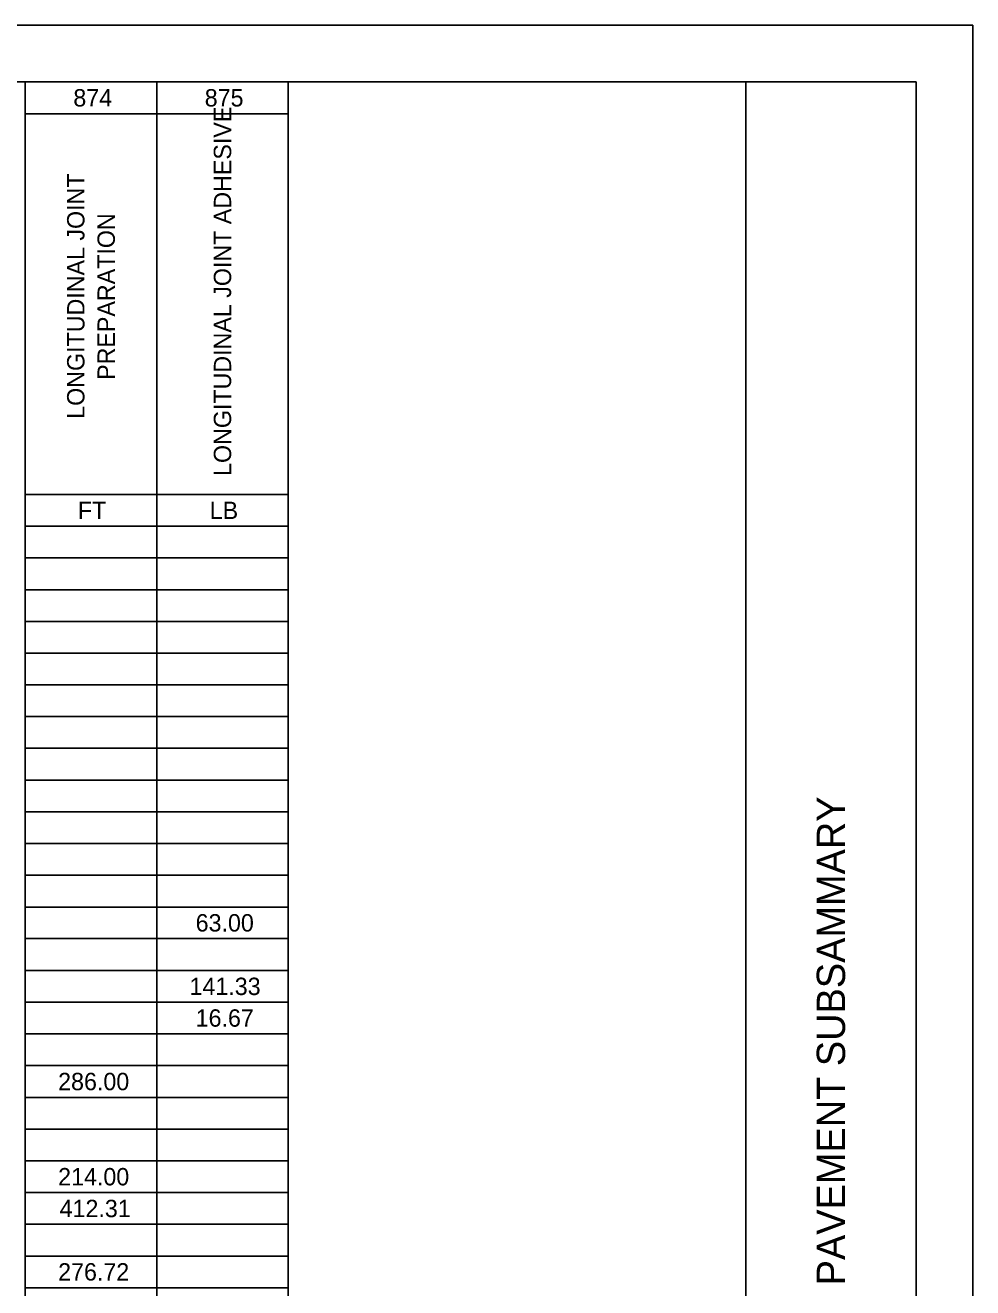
# Model space of a CAD drawing. Extents: x 0 to 34, y 0 to 22.
# Drawn here: x 25.65 to 34, y 10.87 to 22 of the extents above; entities that cross this region are included whole.
import ezdxf

# ---------------------------------------------------------------- set-up
doc = ezdxf.new("R2010")
doc.units = 0
for name, color, linetype in [('SH_Border', 7, 'Continuous'), ('SH_Cut_Line', 7, 'Continuous'), ('SH_Data', 7, 'Continuous'), ('SH_Text', 7, 'Continuous')]:
    doc.layers.add(name, color=color, linetype=linetype)

msp = doc.modelspace()

# ---------------------------------------------------------------- linework, layer by layer
at = {"layer": 'SH_Border'}
msp.add_line((32, 0.5), (32, 21.5), dxfattribs=at)
msp.add_lwpolyline([(1.5, 21.5), (33.5, 21.5), (33.5, 0.5), (1.5, 0.5)], close=True, dxfattribs=at)
at = {"layer": 'SH_Cut_Line'}
msp.add_lwpolyline([(0, 0), (34, 0), (34, 22), (0, 22)], close=True, dxfattribs=at)
at = {"layer": 'SH_Text'}
for p, q in [((25.649, 21.5), (27.967, 21.5)), ((25.649, 21.5), (25.649, 21.22)), ((26.808, 21.5), (26.808, 21.22)), ((27.967, 21.5), (27.967, 21.22)), ((25.649, 21.22), (27.967, 21.22)), ((25.649, 21.22), (25.649, 20.941)), ((26.808, 21.22), (26.808, 20.941)), ((27.967, 21.22), (27.967, 20.941)), ((25.649, 20.941), (25.649, 20.661)), ((26.808, 20.941), (26.808, 20.661)), ((27.967, 20.941), (27.967, 20.661)), ((25.649, 20.661), (25.649, 20.381)), ((26.808, 20.661), (26.808, 20.381)), ((27.967, 20.661), (27.967, 20.381)), ((25.649, 20.381), (25.649, 20.101)), ((26.808, 20.381), (26.808, 20.101)), ((27.967, 20.381), (27.967, 20.101)), ((25.649, 20.101), (25.649, 19.822)), ((26.808, 20.101), (26.808, 19.822)), ((27.967, 20.101), (27.967, 19.822)), ((25.649, 19.822), (25.649, 19.542)), ((26.808, 19.822), (26.808, 19.542)), ((27.967, 19.822), (27.967, 19.542)), ((25.649, 19.542), (25.649, 19.262)), ((26.808, 19.542), (26.808, 19.262)), ((27.967, 19.542), (27.967, 19.262)), ((25.649, 19.262), (25.649, 18.983)), ((26.808, 19.262), (26.808, 18.983)), ((27.967, 19.262), (27.967, 18.983)), ((25.649, 18.983), (25.649, 18.703)), ((26.808, 18.983), (26.808, 18.703)), ((27.967, 18.983), (27.967, 18.703)), ((25.649, 18.703), (25.649, 18.423)), ((26.808, 18.703), (26.808, 18.423)), ((27.967, 18.703), (27.967, 18.423)), ((25.649, 18.423), (25.649, 18.143)), ((26.808, 18.423), (26.808, 18.143)), ((27.967, 18.423), (27.967, 18.143)), ((25.649, 18.143), (25.649, 17.864)), ((26.808, 18.143), (26.808, 17.864)), ((27.967, 18.143), (27.967, 17.864)), ((25.649, 17.864), (27.967, 17.864)), ((25.649, 17.864), (25.649, 17.584)), ((26.808, 17.864), (26.808, 17.584)), ((27.967, 17.864), (27.967, 17.584)), ((25.649, 17.584), (27.967, 17.584)), ((25.649, 17.584), (25.649, 17.304)), ((26.808, 17.584), (26.808, 17.304)), ((27.967, 17.584), (27.967, 17.304)), ((25.649, 17.304), (27.967, 17.304)), ((25.649, 17.304), (25.649, 17.024)), ((26.808, 17.304), (26.808, 17.024)), ((27.967, 17.304), (27.967, 17.024)), ((25.649, 17.024), (27.967, 17.024)), ((25.649, 17.024), (25.649, 16.745)), ((26.808, 17.024), (26.808, 16.745)), ((27.967, 17.024), (27.967, 16.745)), ((25.649, 16.745), (27.967, 16.745)), ((25.649, 16.745), (25.649, 16.465)), ((26.808, 16.745), (26.808, 16.465)), ((27.967, 16.745), (27.967, 16.465)), ((25.649, 16.465), (27.967, 16.465)), ((25.649, 16.465), (25.649, 16.185)), ((26.808, 16.465), (26.808, 16.185)), ((27.967, 16.465), (27.967, 16.185)), ((25.649, 16.185), (27.967, 16.185)), ((25.649, 16.185), (25.649, 15.906)), ((26.808, 16.185), (26.808, 15.906)), ((27.967, 16.185), (27.967, 15.906)), ((25.649, 15.906), (27.967, 15.906)), ((25.649, 15.906), (25.649, 15.626)), ((26.808, 15.906), (26.808, 15.626)), ((27.967, 15.906), (27.967, 15.626)), ((25.649, 15.626), (27.967, 15.626)), ((25.649, 15.626), (25.649, 15.346)), ((26.808, 15.626), (26.808, 15.346)), ((27.967, 15.626), (27.967, 15.346)), ((25.649, 15.346), (27.967, 15.346)), ((25.649, 15.346), (25.649, 15.066)), ((26.808, 15.346), (26.808, 15.066)), ((27.967, 15.346), (27.967, 15.066)), ((25.649, 15.066), (27.967, 15.066)), ((25.649, 15.066), (25.649, 14.787)), ((26.808, 15.066), (26.808, 14.787)), ((27.967, 15.066), (27.967, 14.787)), ((25.649, 14.787), (27.967, 14.787)), ((25.649, 14.787), (25.649, 14.507)), ((26.808, 14.787), (26.808, 14.507)), ((27.967, 14.787), (27.967, 14.507)), ((25.649, 14.507), (27.967, 14.507)), ((25.649, 14.507), (25.649, 14.227)), ((26.808, 14.507), (26.808, 14.227)), ((27.967, 14.507), (27.967, 14.227)), ((25.649, 14.227), (27.967, 14.227)), ((25.649, 14.227), (25.649, 13.948)), ((26.808, 14.227), (26.808, 13.948)), ((27.967, 14.227), (27.967, 13.948)), ((25.649, 13.948), (27.967, 13.948)), ((25.649, 13.948), (25.649, 13.668)), ((26.808, 13.948), (26.808, 13.668)), ((27.967, 13.948), (27.967, 13.668)), ((25.649, 13.668), (27.967, 13.668)), ((25.649, 13.668), (25.649, 13.388)), ((26.808, 13.668), (26.808, 13.388)), ((27.967, 13.668), (27.967, 13.388)), ((25.649, 13.388), (27.967, 13.388)), ((25.649, 13.388), (25.649, 13.108)), ((26.808, 13.388), (26.808, 13.108)), ((27.967, 13.388), (27.967, 13.108)), ((25.649, 13.108), (27.967, 13.108)), ((25.649, 13.108), (25.649, 12.829)), ((26.808, 13.108), (26.808, 12.829)), ((27.967, 13.108), (27.967, 12.829)), ((25.649, 12.829), (27.967, 12.829)), ((25.649, 12.829), (25.649, 12.549)), ((26.808, 12.829), (26.808, 12.549)), ((27.967, 12.829), (27.967, 12.549)), ((25.649, 12.549), (27.967, 12.549)), ((25.649, 12.549), (25.649, 12.269)), ((26.808, 12.549), (26.808, 12.269)), ((27.967, 12.549), (27.967, 12.269)), ((25.649, 12.269), (27.967, 12.269)), ((25.649, 12.269), (25.649, 11.99)), ((26.808, 12.269), (26.808, 11.99)), ((27.967, 12.269), (27.967, 11.99)), ((25.649, 11.99), (27.967, 11.99)), ((25.649, 11.99), (25.649, 11.71)), ((26.808, 11.99), (26.808, 11.71)), ((27.967, 11.99), (27.967, 11.71)), ((25.649, 11.71), (27.967, 11.71)), ((25.649, 11.71), (25.649, 11.43)), ((26.808, 11.71), (26.808, 11.43)), ((27.967, 11.71), (27.967, 11.43)), ((25.649, 11.43), (27.967, 11.43)), ((25.649, 11.43), (25.649, 11.15)), ((26.808, 11.43), (26.808, 11.15)), ((27.967, 11.43), (27.967, 11.15)), ((25.649, 11.15), (27.967, 11.15)), ((25.649, 11.15), (25.649, 10.871)), ((26.808, 11.15), (26.808, 10.871)), ((27.967, 11.15), (27.967, 10.871)), ((25.649, 10.871), (27.967, 10.871)), ((25.649, 10.871), (25.649, 10.591)), ((26.808, 10.871), (26.808, 10.591)), ((27.967, 10.871), (27.967, 10.591))]:
    msp.add_line(p, q, dxfattribs=at)

# ---------------------------------------------------------------- texts
at = {"layer": 'SH_Data'}
msp.add_text('PAVEMENT SUBSAMMARY', height=0.25, rotation=90, dxfattribs=at).set_placement((32.875, 10.892))
at = {"layer": 'SH_Text'}
for s, p in [('874', (26.073, 21.284)), ('875', (27.231, 21.284)), ('FT', (26.113, 17.647)), ('LB', (27.275, 17.647)), ('63.00', (27.151, 14.011)), ('141.33', (27.097, 13.451)), ('16.67', (27.151, 13.172)), ('286.00', (25.939, 12.612)), ('214.00', (25.939, 11.773)), ('412.31', (25.952, 11.493)), ('276.72', (25.939, 10.934))]:
    msp.add_text(s, height=0.1532, dxfattribs=at).set_placement(p)
for s, p in [('LONGITUDINAL JOINT ADHESIVE', (27.464, 18.027)), ('LONGITUDINAL JOINT ', (26.171, 18.531)), ('PREPARATION', (26.439, 18.874))]:
    msp.add_text(s, height=0.15318, rotation=90, dxfattribs=at).set_placement(p)

doc.saveas('drawing.dxf')
